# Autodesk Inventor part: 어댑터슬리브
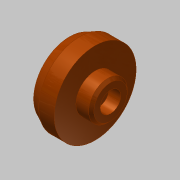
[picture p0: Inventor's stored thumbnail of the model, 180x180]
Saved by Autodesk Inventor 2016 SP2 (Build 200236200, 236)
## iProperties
Created: 2016-06
Part Number: 어댑터슬리브
Material: 강철, 탄소
Document SubType Name: Modeling
Designer: mduedu
Density: 7.87 g/cm^3
Appearance: 매끄러움 - 연한 주황색
Author: mduedu
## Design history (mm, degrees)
sketch "스케치2"
  geometry: L1 (0, 0)-(0, 14); L2 (0, 14)-(-4, 16); L3 (-4, 16)-(-10, 16); L4 (-10, 16)-(-10, 7.5); L5 (-10, 7.5)-(-16, 7.5); L6 (-16, 7.5)-(-16, 0); L7 (-16, 0)-(0, 0)
  constraints: 14 end point, 4 parallel, 1 perpendicular, 1 vertical
  dimensions: "d0" = 32 diameter of L3 L7; "d2" = 28 diameter of L1.end L7; "d3" = 6 distance of L2.end L3.end; "d4" = 6 distance of L4.end L5.end; "d5" = 15 diameter of L5 L7; "d6" = 16 distance between parallel lines of L6 L1
revolve "회전1" sketch "스케치2" stored, may be unused: angle "d7" = 90 deg
sketch "스케치3"
  geometry: L1 (-16, -7.5)-(-16, 7.5) reference; L2 (-16, 7.5)-(-10, 7.5) reference; L3 (-10, 7.5)-(-10, 16) reference; L4 (-10, 16)-(-4, 16) reference; L5 (-4, 16)-(0, 14) reference; L6 (0, 14)-(0, -14) reference; L7 (0, -14)-(-4, -16) reference; L8 (-4, -16)-(-10, -16) reference; L9 (-10, -16)-(-10, -7.5) reference; L10 (-10, -7.5)-(-16, -7.5) reference; L11 (0, 10)-(-5, 10); L12 (-5, 10)-(-5, 8); L13 (-5, 8)-(-7, 6); L14 (-7, 6)-(-7, 0); L15 (-7, 0)-(0, 0); L16 (0, 10)-(0, 0)
  constraints: 12 end point, 3 parallel, 2 perpendicular, 1 point on line
  dimensions: "d8" = 20 diameter of L11 L15; "d10" = 16 diameter of L12.end L15; "d11" = 12 diameter of L13.end L15; "d12" = 9 distance between parallel lines of L14 L1; "d13" = 2 distance between parallel lines of L12 L14
revolve "회전2" sketch "스케치3" stored, may be unused: angle "d14" = 90 deg
chamfer "모따기1" distance "d15" = 1; stored, may be unused: second distance "d16" = 2, angle "d17" = 45 deg
sketch "스케치4"
  geometry: 2 further points
  constraints: 1 coincident
sketch "스케치5"
  geometry: 1 further point
hole "구멍1" sketch "스케치5" at (0, 0) diameter "d18" = 4.5; stored, may be unused: countersink angle "d22" = 90 deg, drill point angle "d24" = 0 deg; dims "d19" = 6, "d20" = 8, "d21" = 4.6, "d23" = 8
node "솔리드1"
node "절단 모서리 투영1"
